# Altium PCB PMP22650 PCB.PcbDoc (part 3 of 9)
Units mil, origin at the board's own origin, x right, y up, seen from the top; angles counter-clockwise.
Board outline 11311 x 5233 mil, 8 copper layers (Layer 1, Layer 2, Layer 3, Layer 4, Layer 5, Layer 6, Layer 7, Layer 8), stack 88.6 mil thick; 633 components, 410 nets, 2503 pads, 1993 vias.
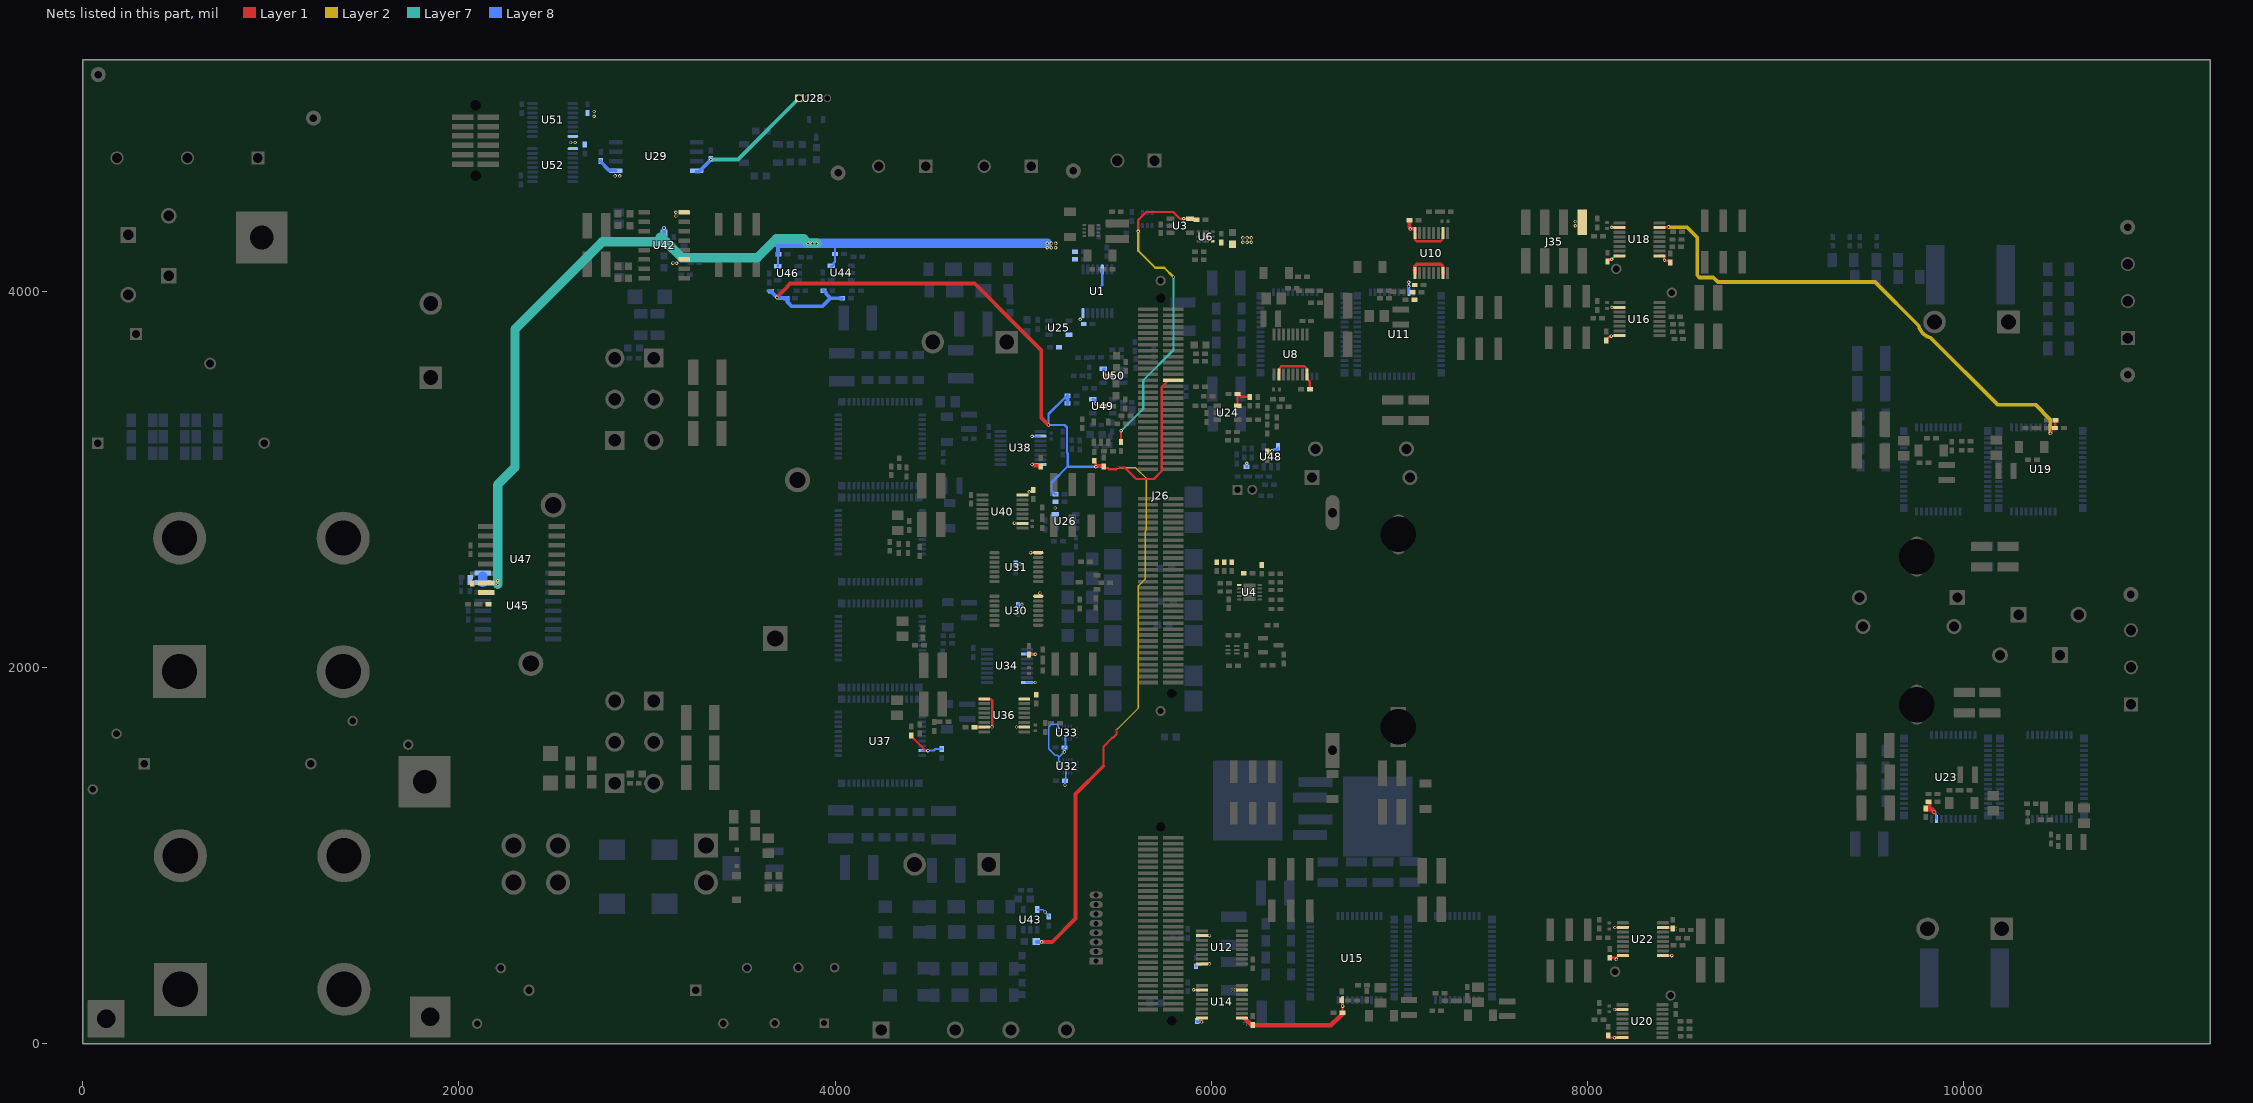
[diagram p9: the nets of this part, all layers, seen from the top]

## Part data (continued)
C44 C59 C66 C81 C88 C103 C110 C125 C152 C167 C174 C189: library part CMP-0750154-1, "CAP, CERM, 10 µF, 25 V,+/- 10%, X7R, AEC-Q200 Grade 1, 1206", Cap_Case=1206, Manufacturer="Taiyo Yuden", TempCo=X7R, Tolerance_%=10%, Value2=25V, ValueDisplayed=10µF
C45 C46 C49 C50 C67 C68 C71 C72 C89 C90 C93 C94 C111 C112 C115 C116 C153 C154 C157 C158 C175 C176 C179 C180 C256 C257: library part CMP-0084048-1, "CAP, CERM, 0.022 µF, 1000 V,+/- 10%, X7R, AEC-Q200 Grade 1, 1206", Cap_Case=1206, Manufacturer=Kemet, TempCo=X7R, Tolerance_%=10%, Value2=1000V, ValueDisplayed=0.022µF
C47 C48 C51 C52 C69 C70 C73 C74 C91 C92 C95 C96 C113 C114 C117 C118 C155 C156 C159 C160 C177 C178 C181 C182 C226 C227 C228 C229 C230 C231: library part CMP-0090548-1, "0.1µF ±10% 1000V (1kV) Ceramic Capacitor X7R 1812 (4532 Metric)", Digikey Part Number=399-16796-1-ND, Manufacturer=Kemet, Mouser Part Number=80-C1812X104KDRAUTO, Operating Temperature Range="-55°C to +125°C", TempCo=15%, Temperature Characteristic=X7R, Tolerance_%=10%, ValueDisplayed=0.1uF
C127 C130 C135 C237 C240: library part CMP-0064911-2, "CAP, CERM, 10 pF, 50 V,+/- 2.5%, C0G/NP0, AEC-Q200 Grade 1, 0402", Cap_Case=0402, Manufacturer=AVX, Supplier Part Number 1=478-5991-1-ND, TempCo=C0G/NP0, Tolerance_%=2.5%, Value1=Unknown, Value2=50V, ValueDisplayed=10pF
C128 C195 C238: library part CMP-0006317-2, "CAP, CERM, 2200 pF, 50 V, +/- 10%, X7R, AEC-Q200 Grade 1, 0402", Cap_Case=0402, Manufacturer=TDK, Supplier Part Number 1=445-5606-1-ND, TempCo=X7R, Tolerance_%=10%, Value1="1.07794 ohm", Value2=50V, ValueDisplayed=2200pF
C131: library part CMP-0006360-2, "CAP, CERM, 470 pF, 50 V, +/- 10%, X7R, AEC-Q200 Grade 1, 0402", Cap_Case=0402, Manufacturer=MuRata, Supplier Part Number 1=490-4913-1-ND, TempCo=X7R, Tolerance_%=10%, Value1=Unknown, Value2=50V, ValueDisplayed=470pF
C138: library part CMP-0007088-4, "CAP, CERM, 4700 pF, 100 V, +/- 10%, X7R, AEC-Q200 Grade 1, 0603", Cap_Case=0603, Manufacturer=TDK, Supplier Part Number 1=445-5810-1-ND, TempCo=X7R, Tolerance_%=10%, Value1="0.469862 ohm", Value2=100V, ValueDisplayed=4700pF
C141 C207 C210: library part CMP-0007127-4, "CAP, CERM, 470 pF, 50 V, +/- 5%, C0G/NP0, AEC-Q200 Grade 1, 0603", Cap_Case=0603, Manufacturer=MuRata, Supplier Part Number 1=490-4965-1-ND, TempCo=C0G/NP0, Tolerance_%=5%, Value1=Unknown, Value2=50V, ValueDisplayed=470pF
C190 C199: library part CMP-0076706-1, "CAP, CERM, 4.7 µF, 25 V,+/- 10%, X7R, AEC-Q200 Grade 1, 0805", Cap_Case=2x1.25x1.25mm, Manufacturer=TDK, Supplier Part Number 1=445-6967-1-ND, TempCo=X7R, Tolerance_%=10%, Value2=25V, ValueDisplayed=4.7µF
C191 C198 C200: library part CMP-0007077-5, "CAP, CERM, 0.1 uF, 25 V, +/- 10%, X7R, AEC-Q200 Grade 1, 0603", Cap_Case=0603, Manufacturer=TDK, Supplier Part Number 1=445-5667-1-ND, TempCo=X7R, Tolerance_%=10%, Value1=Unknown, Value2=25V, ValueDisplayed=0.1uF
C192 C201: library part CMP-0006849-4, "CAP, CERM, 0.01 uF, 25 V, +/- 5%, C0G/NP0, AEC-Q200 Grade 1, 0603", Cap_Case=0603, Manufacturer=Kemet, Supplier Part Number 1=399-14102-1-ND, TempCo=C0G/NP0, Tolerance_%=5%, Value1=Unknown, Value2=25V, ValueDisplayed=0.01uF
C193 C194: library part CMP-0007075-4, "CAP, CERM, 100 pF, 50 V, +/- 5%, C0G/NP0, AEC-Q200 Grade 0, 0603", Cap_Case=0603, Manufacturer=TDK, Supplier Part Number 1=445-12386-1-ND, TempCo=C0G/NP0, Tolerance_%=5%, Value1=Unknown, Value2=50V, ValueDisplayed=100pF
C196 C197: library part CMP-0006314-2, "CAP, CERM, 1000 pF, 50 V, +/- 10%, X7R, AEC-Q200 Grade 1, 0402", Cap_Case=0402, Manufacturer=TDK, Supplier Part Number 1=445-5605-1-ND, TempCo=X7R, Tolerance_%=10%, Value1="2.25564 ohm", Value2=50V, ValueDisplayed=1000pF
C204 C211: library part CMP-0006308-2, "CAP, CERM, 100 pF, 50 V, +/- 5%, C0G/NP0, AEC-Q200 Grade 1, 0402", Cap_Case=0402, Manufacturer=TDK, Supplier Part Number 1=445-5596-1-ND, TempCo=C0G/NP0, Tolerance_%=5%, Value1=Unknown, Value2=50V, ValueDisplayed=100pF
C208 C215: library part CMP-0006237-2, "CAP, CERM, 0.1 uF, 16 V, +/- 10%, X7R, AEC-Q200 Grade 1, 0402", Cap_Case=0402, Manufacturer=Kemet, Supplier Part Number 1=399-6828-1-ND, TempCo=X7R, Tolerance_%=10%, Value1=Unknown, Value2=16V, ValueDisplayed=0.1uF
C213: library part CMP-0006844-4, "CAP, CERM, 1000 pF, 50 V, +/- 5%, X7R, AEC-Q200 Grade 1, 0603", Cap_Case=0603, Manufacturer=Kemet, Supplier Part Number 1=399-12989-1-ND, TempCo=X7R, Tolerance_%=5%, Value1=Unknown, Value2=50V, ValueDisplayed=1000pF
C214: library part CMP-0007965-2, "CAP, CERM, 10 uF, 16 V, +/- 10%, X7S, AEC-Q200 Grade 1, 0805", Cap_Case=0805, Manufacturer=TDK, Supplier Part Number 1=445-16110-1-ND, TempCo=X7S, Tolerance_%=10%, Value1=Unknown, Value2=16V, ValueDisplayed=10uF
C216 C217 C221 C222 C235: library part CMP-0009589-2, "CAP, CERM, 4700 pF, 300 V, +/- 20%, Y5U, AEC-Q200 Grade 1, D13xT5mm", Cap_Case=13x5mm, Manufacturer=Vishay-Bccomponents, Supplier Part Number 1=BC2916-ND, TempCo=Y5U, Tolerance_%=20%, Value1=Unknown, Value2=300V, ValueDisplayed=4700pF
C218 C219 C220: library part CMP-0090606-1, "2.2µF Film Capacitor 305V 630V Polypropylene (PP), Metallized Radial", Digikey Part Number=495-7043-ND, Manufacturer=TDK, Operating Temperature Range="to +110°C", Tolerance_%=20%, ValueDisplayed=2.2uF, Voltage Ac Rating X=305V
C223 C224 C225: library part CMP-0090234-1, "470µF 500V Aluminum Electrolytic Capacitors Radial, Can - Snap-In 532.2mOhm @ 100Hz 15000 Hrs @ 85°C", Digikey Part Number=399-17944-ND, Leakage Current=6uA, Manufacturer=Kemet, Mouser Part Number=80-ALA7DA471DE500, Operating Temperature Range="-40°C to +85°C", Tolerance_%=20%, ValueDisplayed=470uF
C232: library part CMP-0006307-2, "CAP, CERM, 10 pF, 50 V, +/- 5%, C0G/NP0, AEC-Q200 Grade 1, 0402", Cap_Case=0402, Manufacturer=TDK, Supplier Part Number 1=445-5584-1-ND, TempCo=C0G/NP0, Tolerance_%=5%, Value1=Unknown, Value2=50V, ValueDisplayed=10pF
C233: library part CMP-0006310-2, "CAP, CERM, 150 pF, 50 V, +/- 5%, C0G/NP0, AEC-Q200 Grade 1, 0402", Cap_Case=0402, Manufacturer=TDK, Supplier Part Number 1=445-5598-1-ND, TempCo=C0G/NP0, Tolerance_%=5%, Value1=Unknown, Value2=50V, ValueDisplayed=150pF
C234: library part CMP-0090605-2, "100pF ±10% 440VAC Ceramic Capacitor Y5S Radial, Disc", Digikey Part Number=BC2908-ND, Manufacturer=Vishay, Mouser Part Number=72-AY2101K29Y5SS63L7, Operating Temperature Range="-55°C to +125°C", Temperature Characteristic=Y5S, Tolerance_%=10%, ValueDisplayed=100pF, Voltage Ac Rating X=X1, Voltage Ac Rating Y=Y2
C241 C246: library part CMP-0006328-2, "CAP, CERM, 0.022 uF, 50 V, +/- 10%, X7R, AEC-Q200 Grade 1, 0402", Cap_Case=0402, Manufacturer=TDK, Supplier Part Number 1=445-6895-1-ND, TempCo=X7R, Tolerance_%=10%, Value1="0.141987 ohm", Value2=50V, ValueDisplayed=0.022uF
C242 C243 C245 C247 C248 C250: library part CMP-0006324-2, "CAP, CERM, 0.01 uF, 50 V, +/- 10%, X7R, AEC-Q200 Grade 1, 0402", Cap_Case=0402, Manufacturer=TDK, Supplier Part Number 1=445-6893-1-ND, TempCo=X7R, Tolerance_%=10%, Value1="0.333065 ohm", Value2=50V, ValueDisplayed=0.01uF
D1: library part CMP-0005919-3, "Diode, TVS, Bi, 24 V, SOT-23", Manufacturer="ON Semiconductor", Value1=350W
D2 D3: library part CMP-0090591-1, "Diode Schottky 40V 3A Surface Mount SMA", Digikey Part Number=NRVBA340T3GOSCT-ND, Forward Current=3A, Manufacturer="ON Semiconductor", Max Surge Forward Current=100A, Mouser Part Number=863-NRVBA340T3G, Operating Temperature Range="-55°C to +150°C", Peak Reverse Current=0.3mA
D4 D5 D6 D7: library part CMP-0089095-1, "Diode Standard 1000V 1A Surface Mount D-Flat", Digikey Part Number=US1MDFQ-13DICT-ND, Forward Current=1A, Manufacturer=Diodes, Max Surge Forward Current=30A, Mouser Part Number=621-US1MDFQ-13, Operating Temperature Range="-55°C to +150°C", Peak Reverse Current=5uA, ValueDisplayed=10pF
D8: library part CMP-0028882-2, "Diode, Schottky, 40 V, 0.75 A, AEC-Q101, SOD-323", Manufacturer="Infineon Technologies", Value1=0.75A, Value2=0.74V
D9: library part CMP-0065110-3, "Diode, Zener, 5.1 V, 500 mW, AEC-Q101, SOD-123", Manufacturer=Vishay-Semiconductor, Power_W=500mW, Value1=0.5W
D10: library part CMP-0090610-1, "Bridge Rectifier Single Phase Standard 600V Through Hole TS-6P", Digikey Part Number=TS40P05GHD2G-ND, Forward Current=40A, Manufacturer="Taiwan Semiconductor", Max Surge Forward Current=400A, Mouser Part Number=821-TS40P05GHD2G, Operating Temperature Range="-55°C to +150°C", Peak Reverse Current=10uA
F1 F2 F3 F4: library part CMP-4956-0000-1, "25A AC 450V DC Fuse Cartridge, Ceramic Through Hole 3AB, 3AG, 1/4\" x 1-1/4\" (Axial)", Digikey Part Number=F10249-ND, Fuse Current=25A, Fuse Interrupt Dc Current=10000A, Manufacturer=Littelfuse, Mouser Part Number=576-0525025.MXEP, Operating Temperature Range="-55°C to +125°C"
J1: library part CMP-0090793-1, "Connector Header Through Hole 2 position 0.079\" (2.00mm)", Current_A=4A, Digikey Part Number=A98588-ND, Manufacturer="TE Connectivity", Mouser Part Number=571-2921612, Operating Temperature Range="-40°C to +221°C", Voltage_V=125V
J2 J3 J4 J5 J6 J8 J9 J11: library part CMP-0075177-1, "JUMPER TIN SMD, SMT", Current_A=10A, Manufacturer=Harwin, Supplier Part Number 1=952-1474-1-ND
J7 J10: library part CMP-0054983-1, "Receptacle, 3x1, 5mm, R/A, TH", Color=Green, Current_A=24A, Manufacturer="On Shore Technology Inc.", PartNumber=ED700/3, Voltage_V=300V
J12 J16 J18 J20 J22 J27 J29 J31 J36: library part CMP-0055666-1, "Receptacle, 2.54mm, 3x2, Tin, SMT", Color=Black, Current_A=5.7A, Manufacturer=Samtec, Supplier Part Number 1=82P2245
J13 J17 J19 J21 J23 J28 J30 J32: library part CMP-0090790-1, "4 Position Receptacle Connector  Surface Mount", Current_A=4.7A, Digikey Part Number=SSW-102-22-F-D-VS-ND, Manufacturer=Samtec, Mouser Part Number=200-SSW10222FDVS, Operating Temperature Range="-55°C to +125°C", Voltage_V=655V
J15: library part CMP-0054978-1, "Therminal Block, 5 mm, 2-pole, Tin, TH", Manufacturer="On Shore Technology Inc.", PartNumber=ED700/2
J24: library part CMP-0075601-2, "Header(Shrouded), 1.27mm, 6x2, Tin, SMT", Color=Black, Current_A=3.2A, Manufacturer=Samtec, Voltage_V=250V
J25: library part CMP-0003859-2, "C2000 controlCARD-180HSEC (60-pin addon) connector, SMT", Manufacturer=Samtec
J26: library part CMP-0003814-2, "C2000 controlCARD-120HSEC connector, SMT", Manufacturer=Samtec
J33: library part CMP-0055493-1, "Terminal Block, 3x1, 9.52MM, TH", Manufacturer="Phoenix Contact", Supplier Part Number 1=277-1272-ND
J34: library part CMP-0055072-1, "Female Connector, 8x1, 1.27 mm, Black, Tin, TH", Manufacturer=Mill-Max, Supplier Part Number 1=ED90570-ND
J35: library part CMP-0090885-1, "8 Position Receptacle Connector  Surface Mount", Current_A=4.7A, Digikey Part Number=SSW-104-22-F-D-VS-K-ND, Manufacturer=Samtec, Mouser Part Number=200-SSW10422FDVSK, Operating Temperature Range="-55°C to +125°C", Voltage_V=655V
J37 J38: library part CMP-0055505-1, "Terminal Block, 2x1, 6.35mm, Green, TH", Color=Green, Manufacturer="Phoenix Contact", Supplier Part Number 1=277-1269-ND
K1: library part CMP-0090589-1, "Relay Automotive SPST-NO 32A 12VDC 160 Ohm Through Hole", Coil Power_W=440mW, Coil Resistance=160Ω, Coil Voltage_VDC=12V, Contact Rating_A=32A, Manufacturer=Fujitsu, Max Power Dissipation=900mW, Operating Temperature Range="-40°C to +105°C", Switching Current=40A
L2: library part CMP-0056750-1, "Inductor, Shielded, Ferrite, 2.2 uH, 1.7 A, 0.072 ohm, AEC-Q200 Grade 1, SMD", Manufacturer=Bourns, Supplier Part Number 1=SRN3015TA-2R2MCT-ND, Value1="0.072 ohm", Value2=1.7A, ValueDisplayed=2.2uH
L3 L4 L5 L6 L7 L8 L9 L10 L12 L13 L14 L15: library part CMP-0090507-1, "4.7µH Shielded Molded Inductor 1.22A 262mOhm Max 1008 (2520 Metric)", Digikey Part Number=283-4799-1-ND, Manufacturer=Eaton, Mouser Part Number=704-MPIA2510V2-4R7-R, Operating Temperature Range="-40°C to +125°C", Self Resonant Frequency=25MHz, Test Frequency=1MHz, Tolerance_%=20%
L11: library part CMP-0062430-2, "Inductor, Ferrite, 100 uH, 0.15 A, 2 ohm, SMD", Manufacturer=TDK, Supplier Part Number 1=445-3959-1-ND, Value1="2 ohm", Value2=0.15A, ValueDisplayed=100uH
L16 L17: library part CMP-0090759-1, "Common Mode Choke", Manufacturer="Renco Electronics", Operating Temperature Range=to, Test Frequency=10kHz
L18: library part CMP-0091444-1, "Coupled PFC", Manufacturer=Cyntec, Operating Temperature Range=to, Test Frequency=100kHz
L19: library part CMP-0090978-1, "OBC Resonant Inductor", Manufacturer=Cyntec, Operating Temperature Range=to, Test Frequency=500kHz
LBL1: library part CMP-0003625-1, "Thermal Transfer Printable Labels, 0.650\" W x 0.200\" H - 10,000 per roll", Manufacturer=Brady, Supplier Part Number 1=97C5133
Logo1: library part CMP-0074838-1, "Texas Instrument Corporate Signature"
Logo2: library part CMP-0074847-1, "FCC_disclaimer"
Logo3: library part CMP-0074769-1
Logo4: library part CMP-0074844-1
LOGO5 LOGO9: library part CMP-0074835-1, "IEC 61010-1 High Voltage Warning"
LOGO6 LOGO8: library part CMP-0074837-1, "IEC 61010-1 Hot Surface Warning"
MP1: library part CMP-0090997-2, "Shield", Manufacturer="Texas Instruments", Operating Temperature Range=to
Q1 Q2: library part CMP-0090447-1, "N-Channel 800V 17A (Tc) 227W (Tc) Surface Mount PG-TO263-3-2", Digikey Part Number=IPB80R290C3AATMA2-ND, Drain To Source Breakdown Voltage=800V, Input Capacitace At Vds="2300pF @ 100V", Manufacturer="Infineon Technologies", Mouser Part Number=726-IPB80R290C3AATMA, Operating Temperature Range="-40°C to +150°C", Power_W=227W, Pulse Drain Current=51A, Typ Forward Diode Voltage=1V
Q3: library part CMP-0077248-1, "MOSFET, N-CH, 20 V, 2.3 A, AEC-Q101, SOT-23", Alternate Manufacturer=None, Manufacturer="Infineon Technologies", Supplier Part Number 1=BSS806NEH6327XTSA1CT-ND, Value1="? ohm", Value2="1.7 nC"
Q4: library part CMP-0090551-1, "P-Channel 30V 3A (Tc) 3W (Tc) Surface Mount SC-70-6 (SOT-363)", Digikey Part Number=SQ1431EH-T1_GE3CT-ND, Drain To Source Breakdown Voltage=-30V, Input Capacitace At Vds="164pF @ -25V", Manufacturer=Vishay, Mouser Part Number=78-SQ1431EH-T1_GE3, Operating Temperature Range="-55°C to +175°C", Power_W=3W, Pulse Drain Current=-12A, Typ Forward Diode Voltage=-0.85V
Q5: library part CMP-0000888-1, "MOSFET, N-CH, 70 V, 3.8 A, AEC-Q101, SOT-223", Alternate Manufacturer=None, Manufacturer="Diodes Inc.", Supplier Part Number 1=ZXMN7A11GCT-ND, Value1=0.1, Value2="7.4 nC"
Q6 Q7 Q8 Q9: library part CMP-0090619-2, "N-Channel 650V 75A (Tc) 595W (Tc) Through Hole TO-247-3", Digikey Part Number=NVHL025N65S3-ND, Drain To Source Breakdown Voltage=713V, Input Capacitace At Vds="7330pF @ 400V", Manufacturer="ON Semiconductor", Mouser Part Number=863-NVHL025N65S3, Operating Temperature Range="-55°C to +150°C", Power_W=595W, Pulse Drain Current=187.5A, Typ Forward Diode Voltage=0.88V
Q10: library part CMP-0000777-1, "MOSFET, N-CH, 60 V, 0.32 A, AEC-Q101, SOT-23", Alternate Manufacturer=None, Manufacturer="ON Semiconductor", Supplier Part Number 1=2V7002KT1GOSCT-ND, Value1=2, Value2="0.7 nC"
R1 R2 R3 R4 R5: library part CMP-0018567-2, "RES, 0.006, 1%, 0.5 W, 1206", Manufacturer=Vishay-Dale, Power_W=500mW, Supplier Part Number 1=WSLD-.006CT-ND, TempCo="110 ppm/C", Tolerance_%=1%, Value2=0.5W, Value_Code=6L000, ValueDisplayed=0.006
R6 R8: library part CMP-0026463-2, "RES, 5.11 k, 1%, 0.063 W, AEC-Q200 Grade 0, 0402", Manufacturer=Vishay-Dale, Power_W=63mW, Supplier Part Number 1=541-5.11KLCT-ND, TempCo="100 ppm/C", Tolerance_%=1%, Value2=0.063W, Value_Code=5k11, ValueDisplayed=5.11k
R7: library part CMP-0026764-1, "RES, 10.0, 1%, 0.063 W, AEC-Q200 Grade 0, 0402", Manufacturer="Stackpole Electronics Inc", Power_W=63mW, Supplier Part Number 1=RMCF0402JT10R0CT-ND, TempCo="100 ppm/C", Tolerance_%=1%, Value2=0.063W, Value_Code=10R0, ValueDisplayed=10.0
R9 R19 R24 R27 R32 R37 R42 R47 R52 R57 R62 R98 R103 R108 R113 R204: library part CMP-0026992-3, "RES, 0, 5%, 0.1 W, AEC-Q200 Grade 0, 0402", Manufacturer=Panasonic, Power_W=100mW, Supplier Part Number 1=P0.0JCT-ND, TempCo="600 ppm/C", Tolerance_%=5%, Value2=0.1W, Value_Code=0000, ValueDisplayed=0
R10 R11 R12 R13 R14 R15 R17 R18 R20 R22 R66 R71 R78 R82 R178 R183 R203: library part CMP-0078779-1, "RES, 10.0 k, 1%, 0.2 W, AEC-Q200 Grade 0, 0402", Manufacturer=Panasonic, Power_W=200mW, Supplier Part Number 1=P17230CT-ND, TempCo="100 ppm/C", Tolerance_%=1%, Value2=0.2W, Value_Code=10k0, ValueDisplayed=10.0k
R16 R69 R70: library part CMP-0026071-3, "RES, 1.00 k, 1%, 0.063 W, AEC-Q200 Grade 0, 0402", Manufacturer=Vishay-Dale, Power_W=63mW, Supplier Part Number 1=541-1.00KLCT-ND, TempCo="100 ppm/C", Tolerance_%=1%, Value2=0.063W, Value_Code=1k00, ValueDisplayed=1.00k
R21: library part CMP-0026048-3, "RES, 178 k, 1%, 0.063 W, AEC-Q200 Grade 0, 0402", Manufacturer=Vishay-Dale, Power_W=63mW, Supplier Part Number 1=541-178KLCT-ND, TempCo="100 ppm/C", Tolerance_%=1%, Value2=0.063W, Value_Code=178k
R23: library part CMP-0026768-2, "RES, 100 k, 0.5%, 0.063 W, AEC-Q200 Grade 0, 0402", Manufacturer=Vishay-Dale, Power_W=63mW, Supplier Part Number 1=541-100KAVCT-ND, TempCo="50 ppm/C", Tolerance_%=0.5%, Value2=0.063W, Value_Code=100k
R25: library part CMP-0026611-3, "RES, 953 k, 1%, 0.063 W, AEC-Q200 Grade 0, 0402", Manufacturer=Vishay-Dale, Power_W=63mW, Supplier Part Number 1=541-953KLCT-ND, TempCo="100 ppm/C", Tolerance_%=1%, Value2=0.063W, Value_Code=953k
R26 R31 R36 R41 R46 R51 R56 R61 R97 R102 R107 R112: library part CMP-0026510-2, "RES, 69.8 k, 1%, 0.063 W, AEC-Q200 Grade 0, 0402", Manufacturer=Vishay-Dale, Power_W=63mW, Supplier Part Number 1=541-69.8KLCT-ND, TempCo="100 ppm/C", Tolerance_%=1%, Value2=0.063W, Value_Code=69k8, ValueDisplayed=69.8k
R28 R33 R38 R43 R48 R53 R58 R63 R99 R104 R109 R114 R131 R137 R138 R146 R153 R155: library part CMP-0025958-3, "RES, 10.0 k, 1%, 0.063 W, AEC-Q200 Grade 0, 0402", Manufacturer=Vishay-Dale, Power_W=63mW, Supplier Part Number 1=541-10.0KLCT-ND, TempCo="100 ppm/C", Tolerance_%=1%, Value2=0.063W, Value_Code=10k0, ValueDisplayed=10.0k
R29 R34 R39 R44 R49 R54 R59 R64 R100 R105 R110 R115: library part CMP-0026902-3, "RES, 300, 5%, 0.063 W, AEC-Q200 Grade 0, 0402", Manufacturer=Vishay-Dale, Power_W=63mW, Supplier Part Number 1=541-300JCT-ND, TempCo="200 ppm/C", Tolerance_%=5%, Value2=0.063W, Value_Code=300R, ValueDisplayed=300
R30 R35 R40 R45 R50 R55 R60 R65 R101 R106 R111 R116: library part CMP-0026404-2, "RES, 49.9, 1%, 0.063 W, AEC-Q200 Grade 0, 0402", Manufacturer=Vishay-Dale, Power_W=63mW, Supplier Part Number 1=541-49.9LCT-ND, TempCo="100 ppm/C", Tolerance_%=1%, Value2=0.063W, Value_Code=49R9, ValueDisplayed=49.9
R67 R176 R179 R205 R206 R207 R208: library part CMP-0026822-3, "RES, 0, 5%, 0.063 W, AEC-Q200 Grade 0, 0402", Manufacturer=Vishay-Dale, Power_W=63mW, Supplier Part Number 1=541-0.0JCT-ND, TempCo="200 ppm/C", Tolerance_%=5%, Value2=0.063W, Value_Code=0000, ValueDisplayed=0
R68 R81 R180: library part CMP-0026454-2, "RES, 56.2, 1%, 0.063 W, AEC-Q200 Grade 0, 0402", Manufacturer=Vishay-Dale, Power_W=63mW, Supplier Part Number 1=541-56.2LCT-ND, TempCo="100 ppm/C", Tolerance_%=1%, Value2=0.063W, Value_Code=56R2, ValueDisplayed=56.2
R72: library part CMP-0026337-2, "RES, 3.65 k, 1%, 0.063 W, AEC-Q200 Grade 0, 0402", Manufacturer=Vishay-Dale, Power_W=63mW, Supplier Part Number 1=541-3.65KLCT-ND, TempCo="100 ppm/C", Tolerance_%=1%, Value2=0.063W, Value_Code=3k65, ValueDisplayed=3.65k
R73 R91 R141 R147: library part CMP-0022599-4, "RES, 7.15 k, 1%, 0.1 W, AEC-Q200 Grade 0, 0603", Manufacturer=Vishay-Dale, Power_W=100mW, Supplier Part Number 1=541-7.15KHCT-ND, TempCo="100 ppm/C", Tolerance_%=1%, Value2=0.1W, Value_Code=7k15, ValueDisplayed=7.15k
R74 R80 R130 R133 R148: library part CMP-0026070-3, "RES, 19.6, 1%, 0.063 W, AEC-Q200 Grade 0, 0402", Manufacturer=Vishay-Dale, Power_W=63mW, Supplier Part Number 1=541-19.6LCT-ND, TempCo="100 ppm/C", Tolerance_%=1%, Value2=0.063W, Value_Code=19R6, ValueDisplayed=19.6
R75 R76 R77 R94 R95 R96 R127 R128 R129 R134 R135 R136 R142 R143 R144 R150 R151 R152: library part CMP-0016927-3, "RES, 365 k, 1%, 0.25 W, AEC-Q200 Grade 0, 1206", Manufacturer=Vishay-Dale, Power_W=250mW, Supplier Part Number 1=541-365KFCT-ND, TempCo="100 ppm/C", Tolerance_%=1%, Value2=0.25W, Value_Code=365k
R79 R83: library part CMP-0026021-3, "RES, 150 k, 1%, 0.063 W, AEC-Q200 Grade 0, 0402", Manufacturer=Vishay-Dale, Power_W=63mW, Supplier Part Number 1=541-150KLCT-ND, TempCo="100 ppm/C", Tolerance_%=1%, Value2=0.063W, Value_Code=150k
R84 R89 R90 R92 R93: library part CMP-0025874-4, "RES, 0, 5%, 0.1 W, AEC-Q200 Grade 0, 0603", Manufacturer=Panasonic, Power_W=100mW, Supplier Part Number 1=P0.0GCT-ND, TempCo="600 ppm/C", Tolerance_%=5%, Value2=0.1W, Value_Code=0000, ValueDisplayed=0
R85 R88: library part CMP-0023343-3, "RES, 0, 1%, 0.1 W, AEC-Q200 Grade 0, 0603", Manufacturer="Stackpole Electronics Inc", Power_W=100mW, Supplier Part Number 1=RMCF0603ZT0R00CT-ND, TempCo=ppm/C, Tolerance_%=1%, Value2=0.1W, Value_Code=0
R86 R87: library part CMP-0022532-4, "RES, 60.4 k, 1%, 0.1 W, AEC-Q200 Grade 0, 0603", Manufacturer=Vishay-Dale, Power_W=100mW, Supplier Part Number 1=541-60.4KHCT-ND, TempCo="100 ppm/C", Tolerance_%=1%, Value2=0.1W, Value_Code=60k4, ValueDisplayed=60.4k
R117 R121: library part CMP-0016745-3, "RES, 1.00, 1%, 0.25 W, AEC-Q200 Grade 0, 1206", Manufacturer=Vishay-Dale, Power_W=250mW, Supplier Part Number 1=53K1855, TempCo="100 ppm/C", Tolerance_%=1%, Value2=0.25W, Value_Code=1R00, ValueDisplayed=1.00
R118 R122: library part CMP-0025701-4, "RES, 10 k, 5%, 0.1 W, AEC-Q200 Grade 0, 0603", Manufacturer=Vishay-Dale, Power_W=100mW, Supplier Part Number 1=541-10KGCT-ND, TempCo="200 ppm/C", Tolerance_%=5%, Value2=0.1W, Value_Code=10k0, ValueDisplayed=10k
R119 R124: library part CMP-0017092-3, "RES, 5.11, 1%, 0.25 W, AEC-Q200 Grade 0, 1206", Manufacturer=Vishay-Dale, Power_W=250mW, Supplier Part Number 1=541-5.11FFCT-ND, TempCo="100 ppm/C", Tolerance_%=1%, Value2=0.25W, Value_Code=5R11, ValueDisplayed=5.11
R120 R123: library part CMP-0027007-2, "RES, 0, 5%, 0.063 W, AEC-Q200 Grade 0, 0402", Manufacturer="KOA Speer", Power_W=63mW, Supplier Part Number 1=660-RK73Z1ETTP, TempCo=ppm/C, Tolerance_%=5%, Value2=0.063W, Value_Code=0000, ValueDisplayed=0
R125 R139: library part CMP-0022377-4, "RES, 3.48 k, 1%, 0.1 W, AEC-Q200 Grade 0, 0603", Manufacturer=Vishay-Dale, Power_W=100mW, Supplier Part Number 1=541-3.48KHCT-ND, TempCo="100 ppm/C", Tolerance_%=1%, Value2=0.1W, Value_Code=3k48, ValueDisplayed=3.48k
R126 R140 R145 R154: library part CMP-0026041-3, "RES, 16.5 k, 1%, 0.063 W, AEC-Q200 Grade 0, 0402", Manufacturer=Vishay-Dale, Power_W=63mW, Supplier Part Number 1=541-16.5KLCT-ND, TempCo="100 ppm/C", Tolerance_%=1%, Value2=0.063W, Value_Code=16k5, ValueDisplayed=16.5k
R132 R149: library part CMP-0026335-2, "RES, 3.48 k, 1%, 0.063 W, AEC-Q200 Grade 0, 0402", Manufacturer=Vishay-Dale, Power_W=63mW, Supplier Part Number 1=541-3.48KLCT-ND, TempCo="100 ppm/C", Tolerance_%=1%, Value2=0.063W, Value_Code=3k48, ValueDisplayed=3.48k
R156: library part CMP-0021998-4, "RES, 10.0 k, 1%, 0.1 W, AEC-Q200 Grade 0, 0603", Manufacturer=Vishay-Dale, Power_W=100mW, Supplier Part Number 1=541-10.0KHCT-ND, TempCo="100 ppm/C", Tolerance_%=1%, Value2=0.1W, Value_Code=10k0, ValueDisplayed=10.0k
R157 R158: library part CMP-0018707-3, "RES, 5.1, 5%, 0.25 W, AEC-Q200 Grade 0, 1206", Manufacturer=Vishay-Dale, Power_W=250mW, Supplier Part Number 1=541-5.1ECT-ND, TempCo="200 ppm/C", Tolerance_%=5%, Value2=0.25W, Value_Code=5R10, ValueDisplayed=5.1
R159 R164 R166 R171 R172: library part CMP-0086941-2, "10 mOhms ±1% 1W Chip Resistor 1206 (3216 Metric) Automotive AEC-Q200, Current Sense, Moisture Resistant Metal Element", Manufacturer=Bourns, Power_W=1W, TempCo=50ppm/°C, Tolerance_%=1%, ValueDisplayed=10m
R160 R165: library part CMP-0090612-1, "PTC Thermistors 30Vdc 185mA 13ohms PTC Overcurrent", Digikey Part Number=495-76340-1-ND, Manufacturer=TDK, Max Current=90mA, Mouser Part Number=871-B59101P1080A062, Operating Temperature Range="-40°C to +125°C", Tolerance_%=25%
R161 R162 R163 R167 R168 R169 R173 R174 R175: library part CMP-0018656-3, "RES, 330 k, 5%, 0.25 W, AEC-Q200 Grade 0, 1206", Manufacturer=Vishay-Dale, Power_W=250mW, Supplier Part Number 1=541-330KECT-ND, TempCo="200 ppm/C", Tolerance_%=5%, Value2=0.25W, Value_Code=330k
R170: library part CMP-0090617-1, "820V 10kA Varistor 1 Circuit Through Hole Disc 20mm", Clamping Voltage=1355V, Digikey Part Number=F10974-ND, Manufacturer=Littelfuse, Mouser Part Number=576-V20H510AUTO, Operating Temperature Range="-40°C to +125°C", ValueDisplayed=350pF, Varistor Voltage=738V
R177: library part CMP-0026088-3, "RES, 1.50 k, 1%, 0.063 W, AEC-Q200 Grade 0, 0402", Manufacturer=Vishay-Dale, Power_W=63mW, Supplier Part Number 1=541-1.50KLCT-ND, TempCo="100 ppm/C", Tolerance_%=1%, Value2=0.063W, Value_Code=1k50, ValueDisplayed=1.50k
R181 R182: library part CMP-0026448-2, "RES, 549, 1%, 0.063 W, AEC-Q200 Grade 0, 0402", Manufacturer=Vishay-Dale, Power_W=63mW, Supplier Part Number 1=541-549LCT-ND, TempCo="100 ppm/C", Tolerance_%=1%, Value2=0.063W, Value_Code=549R, ValueDisplayed=549
R184: library part CMP-0026084-3, "RES, 1.37 k, 1%, 0.063 W, AEC-Q200 Grade 0, 0402", Manufacturer=Vishay-Dale, Power_W=63mW, Supplier Part Number 1=541-1.37KLCT-ND, TempCo="100 ppm/C", Tolerance_%=1%, Value2=0.063W, Value_Code=1k37, ValueDisplayed=1.37k
R185 R191: library part CMP-0022636-4, "RES, 8.45 k, 1%, 0.1 W, AEC-Q200 Grade 0, 0603", Manufacturer=Vishay-Dale, Power_W=100mW, Supplier Part Number 1=541-8.45KHCT-ND, TempCo="100 ppm/C", Tolerance_%=1%, Value2=0.1W, Value_Code=8k45, ValueDisplayed=8.45k
R186 R187 R189 R190: library part CMP-0026238-2, "RES, 2.55 k, 1%, 0.063 W, AEC-Q200 Grade 0, 0402", Manufacturer=Vishay-Dale, Power_W=63mW, Supplier Part Number 1=541-2.55KLCT-ND, TempCo="100 ppm/C", Tolerance_%=1%, Value2=0.063W, Value_Code=2k55, ValueDisplayed=2.55k
R188 R198: library part CMP-0025979-3, "RES, 11.0, 1%, 0.063 W, AEC-Q200 Grade 0, 0402", Manufacturer=Vishay-Dale, Power_W=63mW, Supplier Part Number 1=541-11.0LCT-ND, TempCo="100 ppm/C", Tolerance_%=1%, Value2=0.063W, Value_Code=11R0, ValueDisplayed=11.0
R192: library part CMP-0017331-3, "RES, 12.4 k, 1%, 0.25 W, AEC-Q200 Grade 0, 1206", Manufacturer=Panasonic, Power_W=250mW, Supplier Part Number 1=P12.4KFCT-ND, TempCo="100 ppm/C", Tolerance_%=1%, Value2=0.25W, Value_Code=12k4, ValueDisplayed=12.4k
R193 R197 R201: library part CMP-0016861-3, "RES, 2.00 M, 1%, 0.25 W, AEC-Q200 Grade 0, 1206", Manufacturer=Vishay-Dale, Power_W=250mW, Supplier Part Number 1=541-2.00MFCT-ND, TempCo="100 ppm/C", Tolerance_%=1%, Value2=0.25W, Value_Code=2M00, ValueDisplayed=2.00M
R194 R202: library part CMP-0026553-2, "RES, 7.15 k, 1%, 0.063 W, AEC-Q200 Grade 0, 0402", Manufacturer=Vishay-Dale, Power_W=63mW, Supplier Part Number 1=541-7.15KLCT-ND, TempCo="100 ppm/C", Tolerance_%=1%, Value2=0.063W, Value_Code=7k15, ValueDisplayed=7.15k
R195 R196 R199 R200: library part CMP-0026938-5, "RES, 4.7 k, 5%, 0.063 W, AEC-Q200 Grade 0, 0402", Manufacturer=Vishay-Dale, Power_W=63mW, Supplier Part Number 1=541-4.7KJCT-ND, TempCo="200 ppm/C", Tolerance_%=5%, Value2=0.063W, Value_Code=4k70, ValueDisplayed=4.7k
R209 R210 R211 R212 R213 R214 R215 R216 R217 R218 R219 R220: library part CMP-0026827-3, "RES, 10, 5%, 0.063 W, AEC-Q200 Grade 0, 0402", Manufacturer=Vishay-Dale, Power_W=63mW, Supplier Part Number 1=541-10JCT-ND, TempCo="200 ppm/C", Tolerance_%=5%, Value2=0.063W, Value_Code=10R0, ValueDisplayed=10
T1: library part CMP-0090781-3, "TRANSFORMER", Manufacturer=Cyntec, Operating Temperature Range=to, Voltage_Isolation_Vrms=2000VDC
T2: library part CMP-0090959-1, "PRIMARY SIDE ROGOWSKI (PMP22495)", Manufacturer="Renco Electronics", Operating Temperature Range=to
T3: library part CMP-0090960-2, "Secondary Side Rogowski (PMP22495)", Manufacturer="Renco Electronics", Operating Temperature Range=to
TP1 TP2 TP5 TP6: library part CMP-0055138-1, "Test Point, Miniature, Black, TH", Color=Black, Manufacturer=Keystone, Supplier Part Number 1=36-5001-ND
TP3 TP7 TP8: library part CMP-0055137-1, "Test Point, Miniature, Red, TH", Color=Red, Manufacturer=Keystone, Supplier Part Number 1=36-5000-ND
U1 U30: library part CMP-0054468-2, "Automotive Catalog Dual 4-Input Positive-AND Gates, PW0014A, LARGE T&R", F @ Nom Voltage(Max)(Mhz)=70, Generic Part Number=SN74HC21-Q1, ICC @ Nom Voltage(Max)(mA)=0.02, Manufacturer="Texas Instruments", Operating Temperature Range(C)="-40 to 125", Rating=Automotive, tpd @ Nom Voltage(Max)(ns)=140, Voltage(Nom)(V)=5
U2: library part CMP-0073534-1, "3-MHz, Low-Power, Internal EMI Filter, RRIO, Operational Amplifier, DBV0005A (SOT-23-5)", Alternate Manufacturer="Texas Instruments", Alternate PartNumber=TLV314QDBVTQ1
U3: library part CMP-0090523-1, "Voltage References Automotive 12-ppm/ C low-noise low-power precision voltage reference", Manufacturer="Texas Instruments", Max Supply Voltage=5.5V, Min Supply Voltage=2.8V, Mouser Part Number=595-REF4132B33DBVRQ1, Nominal Supply Current=80uA, Operating Temperature Range="-40°C to +125°C", Output Voltage=3.3V
U4: library part CMP-0081428-2, "Automotive Precision Voltage Supervisor With Programmable Window Watchdog Timer, DRC0010R (VSON-10)", Alternate Manufacturer="Texas Instruments", Operating Temperature Range="-40 to 125 C", Rating=Automotive
U5: library part CMP-0750051-1, "Overvoltage and Undervoltage Reset IC With Time Delay and Manual Reset, DSE0006A (WSON-6)", Alternate Manufacturer="Texas Instruments"
U6: library part CMP-0090683-1, "Linear Voltage Regulator IC  1 Output  500mA 6-WSON (2x2)", Digikey Part Number=296-TPS74533PQWDRVRQ1CT-ND, Dropout Voltage=95mV, Manufacturer="Texas Instruments", Max Supply Voltage=6V, Min Supply Voltage=4.15V, Mouser Part Number=595-PS74533PQWDRVRQ1, Nominal Supply Current=25uA, Operating Temperature Range="-40°C to +125°C", Output Voltage=3.3V
U7: library part CMP-0067104-2, "3-17V 0.5A Automotive Step-Down Converter in 2x2 QFN package, DSG0008A (WSON-8)", Alternate Manufacturer="Texas Instruments", Alternate PartNumber=TPS62170QDSGTQ1
U8 U10 U12 U14 U16 U18 U20 U22 U34 U36 U38 U40: library part CMP-0090469-1, Digikey Part Number=296-51207-1-ND, Manufacturer="Texas Instruments", Max Supply Voltage=5.5V, Min Supply Voltage=2.25V, Mouser Part Number=595-ISO7741FQDBQRQ1, Nominal Supply Current=1.5-18mA, Operating Temperature Range="-40°C to +125°C"
U9 U11 U13 U15 U17 U19 U21 U23 U35 U37 U39 U41: library part CMP-0089968-2, "650-V 30-mΩ GaN FET with Integrated Driver and Protection", Manufacturer="Texas Instruments", Max Supply Voltage=18V, Min Supply Voltage=7.5V, Nominal Supply Current=540uA, Operating Temperature Range="-40°C to +125°C", Output Voltage=520V
U24 U48: library part CMP-0041005-2, "Automotive Catalog, 50 MHz, Low-Noise, Single-Supply Rail-to-Rail Operational Amplifier, 2.2 to 5.5 V, -40 to 125 degC, 5-pin SOT23 (DBV5), Green (RoHS & no Sb/Br)", Manufacturer="Texas Instruments", Total Supply Voltage(Max)(+5V is 5, +/-5V is 10)=5.5, Total Supply Voltage(Min)(+5V is 5, +/-5V is 10)=2.2
U25 U43 U44 U46 U49 U50: library part CMP-0077859-1, "Automotive Qualified Precision, Zero-Crossover, 20MHz, 0.9pA Ib, RRIO, CMOS Operational Amplifier, DBV0005A (SOT-23-5)", Alternate Manufacturer="Texas Instruments", Alternate PartNumber=OPA320AQDBVTQ1
U26: library part CMP-0068826-2, "17 MHz, Low Noise, CMOS Input, 1.8V Operational Amplifiers, DBV0005A (SOT-23-5)", Manufacturer="Texas Instruments", Operating Temperature Range="-40 to 125 C", Rating=Automotive
U27: library part CMP-0090472-1, "Temperature Sensor Analog, Local -40°C ~ 150°C 10mV/°C SOT-23-3", Digikey Part Number=296-TMP235AEDBZTQ1CT-ND, Manufacturer="Texas Instruments", Max Supply Voltage=5.5V, Min Supply Voltage=2.3V, Mouser Part Number=595-TMP235AEDBZTQ1, Operating Supply Current=9uA, Operating Temperature Range="-40°C to +150°C", Output Voltage=500mV
U28: library part CMP-0054569-1, "Header, 50mil, 4x1, Gold, TH", Manufacturer="Sullins Connector Solutions", Supplier Part Number 1=S9014E-04-ND
U29: library part CMP-0090614-1, "Isolated CAN Transceiver with 70V Bus Fault Protection and Flexible Data Rate 8-Pin SOIC T/R", Digikey Part Number=296-ISO1042BQDWVRQ1CT-ND, Manufacturer="Texas Instruments", Max Supply Voltage=5.5V, Min Supply Voltage=1.71V, Mouser Part Number=595-ISO1042BQDWVRQ1, Nominal Supply Current=1.2-43mA, Operating Temperature Range="-40°C to +125°C"
U31: library part CMP-0054514-2, "Automotive Catalog Quadruple 2-Input Positive-AND Gates, PW0014A, LARGE T&R", F @ Nom Voltage(Max)(Mhz)=70, Generic Part Number=SN74AHCT08Q-Q1, ICC @ Nom Voltage(Max)(mA)=0.02, Manufacturer="Texas Instruments", Operating Temperature Range(C)="-40 to 125", Rating=Automotive, tpd @ Nom Voltage(Max)(ns)=9, Voltage(Nom)(V)=5
U32 U33: library part CMP-0090592-1, "Automotive, 5-V bidirectional 8:1 multiplexer with 1.8-V logic", Manufacturer="Texas Instruments", Max Supply Voltage=5.5V, Min Supply Voltage=1.08V, Mouser Part Number=595-TMUX1208QRSVRQ1, Nominal Supply Current=0.02uA, On State Resistance=5Ω, Operating Temperature Range="-40°C to +125°C"
U42: library part CMP-0090594-2, "Half-Bridge Gate Driver IC CMOS/TTL 16-SOIC", Digikey Part Number=296-UCC21222QDRQ1CT-ND, Manufacturer="Texas Instruments", Max Power Dissipation=1825mW, Max Supply Voltage=5.5V, Min Supply Voltage=3V, Mouser Part Number=595-UCC21222QDRQ1, Nominal Supply Current=1-2.5mA, Operating Temperature Range="-40°C to +125°C", Output Voltage=9.2-18V
U45 U47: library part CMP-0090912-1, "Current Sensor 40A 1 Channel Hall Effect, Differential Bidirectional 16-SOIC (0.295\", 7.50mm Width)", Coil Resistance=1mΩ, Current Sensitivity=33mV/A, Digikey Part Number=620-1988-1-ND, Manufacturer="Allegro Microsystems", Max Sensing Current=40A, Max Supply Voltage=3.46V, Min Supply Voltage=3.14V, Operating Supply Current=20mA, Operating Temperature Range="to +165°C"
U51: library part CMP-0078425-1, "High Speed, Robust EMC, Reinforced Six-Channel Digital Isolator, DBQ0016A (SSOP-16)", Alternate Manufacturer="Texas Instruments", Alternate PartNumber=ISO7761DBQ
U52: library part CMP-0013038-3, "High Speed, Robust EMC Reinforced Triple-Channel Digital Isolator, DBQ0016A (SSOP-16)", Alternate Manufacturer="Texas Instruments", Alternate PartNumber=ISO7730DBQ
ZZ1: library part CMP-0077238-1
ZZ2: library part CMP-0077237-1
ZZ3: library part CMP-0077236-1
ZZ4: library part CMP-0003616-3

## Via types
v1: diameter 18, hole 10, Layer 1 to Layer 8, 1759 vias
v2: diameter 8, hole 4, Layer 1 to Layer 2, 160 vias
v3: diameter 18, hole 10, Layer 1 to Layer 8, tented both sides, 34 vias
v4: diameter 8, hole 4, Layer 7 to Layer 8, 28 vias
v5: diameter 19.68, hole 7.87, Layer 1 to Layer 8, 8 vias
v6: diameter 118.11, hole 86.61, Layer 1 to Layer 8, 4 vias

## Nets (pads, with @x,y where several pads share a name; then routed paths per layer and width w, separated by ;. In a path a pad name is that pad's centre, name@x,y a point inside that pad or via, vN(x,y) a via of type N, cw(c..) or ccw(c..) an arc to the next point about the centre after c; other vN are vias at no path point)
1V65_REF: C23.1 C247.1 J26.26 R7.2 R79.1 R125.1 R126.1 R137.1 R145.2 R153.1 R194.1 | length 7342.3
  Layer 1 w12: R7.2@5376.58,3100.66 5376.58,3096.73 5386,3087.31 v1@5386,3069 ; v1(5386.3,3069.04) C23.1@5430.19,3069.04 ; 5389.42,3078.48 5422.77,3078.48 5428.58,3072.66 C23.1@5428.58,3071.04 C23.1@5429.96,3071.04 ; 5425.75,1476.16 5426.46,1476.86 5426.46,1580.87 5473.08,1627.5 5476.83,1627.5 5496,1646.67 v2(5496,1670) ; C23.1@5429.96,3065.73 5433.52,3062.16 5448.71,3062.16 5454.64,3056.23 5493.9,3056.23 v2(5502.27,3064.6) ; v2@5502.27,3064.85 5540.15,3064.85 5601,3004 5694.67,3004 5736.77,3046.1 5736.77,3492.78 5768.5,3524.51 5768.5,3525.39 5794.22,3525.39 J26.26@5797.27,3528.44
  Layer 1 w20: v1(3690.06,3969.54) 3745.51,4024.99 3745.51,4027.78 3760.3,4042.57 4742.24,4042.57 4959.35,3825.46 5095,3689.81 5095,3330.52 v1(5134.79,3290.73) ; v1(5098.27,542.6) 5154.27,542.6 5278.19,666.52 5278.19,1328.59 5425.75,1476.16
  Layer 2 w8: v2(5496,1670) 5612,1786 5612,2436.33 5648,2472.33 5648,2726.3 5654.5,2732.8 5654.5,3005.78 5596.28,3064 v2@5503,3064
  Layer 8 w12: R79.1@5172.26,2922.58 5168.32,2922.58 5150.51,2940.39 5150.51,2984.74 5236.82,3071.04 ; C247.1@5233.27,3447.6 5233.27,3447.37 5225.5,3439.6 5225.27,3439.6 5134.79,3349.12 v1(5134.79,3290.73) 5219.5,3290.73 5232.21,3278.03 5232.21,3144.3 5236.82,3139.69 5236.82,3071.04 ; v1(5386.3,3069.04) 5238.82,3069.04 5236.82,3071.04
  Layer 8 w20: R153.1@3644.98,4004.38 3657.46,4004.38 R153.1@3659.27,4002.57 3663.2,4002.57 3665.02,4000.75 3665.02,3994.58 v1(3690.06,3969.54) 3694.03,3965.57 R145.2@3740.27,3965.57 3744.2,3965.57 3746.02,3963.75 3746.02,3944.16 3768.46,3921.72 3932.41,3921.72 3975.24,3964.55 ; R137.1@3937.07,4004.95 3941.01,4004.95 3953.07,3992.89 3953.07,3986.72 3975.24,3964.55 ; R126.1@4037.57,3964.55 3975.24,3964.55 ; R125.1@5073.27,542.6 v1(5098.27,542.6) ; R194.1@5235.09,3407.6 5235.25,3407.75 C247.1@5235.25,3445.41
3V3_PRI: C22.1 C29.1 C35.2 C36.1 C39.1 C54.1 C61.1 C76.1 C83.1 C98.1 C105.1 C120.1 C129.1 C133.1 C137.1 C139.1 C142.1 C143.1 C144.2 C145.2 C147.1 C162.1 C169.1 C184.1 C198.1 C205.1 C206.1 C208.2 C212.1 C215.2 C239.1 C244.1 C249.1 C251.1 C253.1 J35.2 R13.2 R14.2 R15.2 R20.2 R22.2 R71.2 R138.2 R155.2 R183.2 R203.2 U1.5 U1.14 U4.1 U6.1 U8.10 U8.16 U10.10 U10.16 U12.10 U12.16 U14.10 U14.16 U16.10 U16.16 U18.10 U18.16 U20.10 U20.16 U22.10 U22.16 U24.5 U25.5 U26.5 U29.1 U30.14 U31.14 U32.11 U32.16 U33.11 U33.16 U34.10 U34.16 U36.10 U36.16 U38.10 U38.16 U40.10 U40.16 U42.3 U42.8 U43.5 U44.5 U45.15 U45.16 U46.5 U47.15 U47.16 U48.5 U49.5 U50.5 U51.16 U52.1 | length 7967.4
  Layer 1 w8: v1(4953,2769) 4953.75,2768.25 4998.75,2768.25 U40.10@5001,2766 ; v1(4964,1685) 4964.25,1684.75 5004.75,1684.75 U36.10@5005,1685 ; U40.16@4995.3,2917.5 U40.16@4996.28,2918.48 ; C184.1@5055,2934.68 C184.1@5055,2939 ; v1@5909,288 5909.48,287.52 5946.48,287.52 U14.10@5947,287
  Layer 1 w12: C147.1@5030.57,2069.67 5061.06,2069.67 5063.48,2072.1 v1(5064.57,2072.1) ; v1@5043.27,2612.6 5079.16,2612.6 U31.14@5079.41,2612.35 ; U30.14@5083.27,2382.6 5087.88,2382.6 5088.27,2382.99 v1(5088.27,2397.6) ; v1(5385.01,3403.86) 5386.09,3403.86 5396.8,3393.15 5428,3393.15 C244.1@5430.55,3390.6 ; v1(5948,117) 5948,135.08 U14.16@5949.97,137.05 ; U14.10@5948.27,287.6 5948.82,287.05 U14.10@5949.97,287.05 ; U12.10@5948.27,577.6 5949.82,576.05 U12.10@5949.97,576.05 v1(5989.97,576.05) ; U12.16@5951.72,426.05 v1(5989.97,426.05) ; U24.5@6140.63,3393.86 6139.26,3395.23 6139.26,3454.23 C129.1@6137.89,3455.6 6141.83,3455.6 6156.86,3440.57 R71.2@6204.27,3440.57 ; C239.1@6295,3152 6295.15,3151.85 6320.85,3151.85 v1(6322,3153) ; U8.10@6358.98,3559.74 6361.05,3561.81 6361.05,3591.51 6372.28,3602.74 6495.68,3602.74 6506.91,3591.51 6506.91,3561.81 U8.16@6508.98,3559.74 6508.98,3536.32 6523.56,3521.73 C39.1@6523.56,3479.75 ; U10.16@7081.69,4310.9 7083.76,4308.83 7083.76,4274.93 7090.79,4267.9 7218.39,4267.9 7229.62,4279.13 7229.62,4308.83 U10.10@7231.69,4310.9 ; C83.1@8099,3740.38 8099,3744.32 8116.54,3761.85 8124.15,3761.85 v1@8125,3761 ; C98.1@8106,4159.38 8106,4163.32 8111.81,4169.13 8124.5,4169.13 8126.38,4171 v1@8127,4171 ; C105.1@8110,40 8115.85,34.15 8142.85,34.15 v1(8144,33) 8144.25,33.25 8185.45,33.25 U20.16@8185.7,33.5 ; C120.1@8118,458.38 8143.2,458.38 8150.58,451 v1@8153,451 ; v1(8126,3763) 8127.62,3763 8129.05,3764.43 8167.43,3764.43 U16.16@8168,3765 ; v1@8128,3916 8128.25,3916.25 8169.45,3916.25 U16.10@8169.7,3916.5 ; v1(8129,4172) 8129,4173.22 8146.78,4191 U18.16@8167,4191 ; v1@8130,4340 8131.25,4341.25 8168.95,4341.25 U18.10@8169.7,4340.5 ; v1@8144,184 8144.75,183.25 8185.45,183.25 U20.10@8185.7,183.5 ; v1@8147,618 8147,618.48 8147.77,619.25 8187.45,619.25 U22.10@8187.7,619.5 ; v1(8153,450) 8154.15,451.15 8154.15,459.37 8162.78,468 U22.16@8185,468
  Layer 1 w20: v1@5051.57,3081.1 5057.94,3074.72 5091.46,3074.72 5093.27,3072.91 C169.1@5093.27,3068.98 C169.1@5093.27,3067.6 ; v1(5428.27,3557.6) 5431.74,3554.12 5466.74,3554.12 C249.1@5468.27,3552.6 ; C54.1@7053.65,4378.6 7053.65,4342.22 v1@7057.27,4338.6 ; v1(7057.27,4333.6) U10.16@7082.27,4333.6
  Layer 7 w50: v1@2205,2445 2205,2972.76 2298,3065.76 2298,3800.33 2761.67,4264 3071,4264 ; 3071,4289 3076,4289 3086,4279 ; 3101,4264 3185.5,4179.5 3585.5,4179.5 3687,4281 3831.87,4281 v1(3856.27,4256.6) v1(3878.77,4256.6) v1(3901.27,4256.6)
  Layer 8 w8: v1@5048,3231 5048.1,3231.1 U38.10@5091.57,3231.1 ; v1@5053.27,3077.6 5053.27,3079.1 5055.26,3081.1 U38.16@5091.57,3081.1 ; U43.5@5074.02,714.73 5103.04,714.73 v1(5116.18,701.6) 5136.62,681.16 C205.1@5136.62,677.22 ; U32.16@5179.98,1500.16 5180.04,1500.1 U32.16@5187.79,1500.1 5187.79,1522.12 ; U33.16@5184.93,1677.82 5185,1677.88 5185,1694.31 5180.31,1699 5148,1699 5135.5,1686.5 5135.5,1569.2 5170.6,1534.1 5183.1,1534.1 5187.79,1529.41 5187.79,1522.12 ; v1@5218.27,1377.6 5221.89,1381.22 5221.89,1398.6 5227.16,1403.87 U32.11@5227.16,1444.98 ; v1(5218.27,1552.6) 5187.79,1522.12
  Layer 8 w10: v1@5218.27,1554 5218.27,1562.65 5211.93,1568.98 C145.2@5219.03,1576.09 5224.3,1581.35 U33.11@5224.3,1622.7
  Layer 8 w12: U46.5@3695.04,4134.97 3696.66,4136.58 C212.1@3696.66,4195.95 ; U44.5@3978.35,4136.43 3986.22,4136.43 3992.03,4142.24 3992.03,4150.11 3999.52,4157.6 C206.1@3999.52,4199.95 3999.52,4253.1 3996.02,4256.6 ; C142.1@4963.62,2554.2 4964.45,2553.36 4982.5,2553.36 v1(4983.27,2552.6) ; C143.1@4971.92,2333.72 4971.92,2337.66 C143.1@4977.73,2343.47 ; C143.1@4973.27,2332.6 4977.5,2336.83 4992.5,2336.83 v1(4993.27,2337.6) ; U34.16@5018.27,1922.6 5018.77,1922.1 U34.16@5019.57,1922.1 v1(5064.57,1922.1) ; U34.10@5018.27,2072.6 5018.77,2072.1 U34.10@5019.57,2072.1 v1(5064.57,2072.1) ; v1(5172.27,4256.6) v1@5173.35,4256.6 ; U49.5@5368.51,3428 5376.39,3428 5382.2,3422.19 5382.2,3406.67 v1(5385.01,3403.86) ; 5414.65,4029.58 5420.03,4034.97 U1.5@5420.03,4118 ; U50.5@5426.02,3589.71 U50.5@5433.9,3589.71 ; C61.1@5918.27,413.33 5918.27,417.27 5924.08,423.08 5945.92,423.08 5948.89,426.05 5949.82,426.05 ; C76.1@5921.89,121.51 5925.25,118.15 5946.38,118.15 v1@5948,119.77 ; 5948.27,427.6 5949.82,426.05 ; v1(5989.97,426.05) 5949.82,426.05 ; R183.2@6188,3067 6187.81,3067.19 6187.81,3087.23 v1(6188.25,3087.67) ; v1(6322,3153) 6323.62,3153 6333.07,3162.45 6350.45,3162.45 U48.5@6355,3167
  Layer 8 w20: C139.1@2753.27,4693.98 2753.27,4690.04 2797.9,4645.41 2830.46,4645.41 U29.1@2833.27,4642.6 ; C198.1@3090.27,4304.6 v1(3090.27,4337.6) v1@3090.27,4339.6 ; C212.1@3696.66,4195.95 3696.66,4256.6 ; v1(5428.27,3557.6) U50.5@5428.27,3587.6
  Layer 8 w50: U45.15@2126.26,2453.6 2126.26,2487.87 ; 3696.66,4256.6 v1(3856.27,4256.6) ; v1@3862.55,4256.6 v1(3878.77,4256.6) v1(3901.27,4256.6) 3996.02,4256.6 v1(5127.27,4256.6)
  other v1: 8144,183 5906,288 8145,619 5222,1376 2206.27,2442.6 2206.27,2462.6 5039.41,2612.35 5169.26,2849.6 5032,2935.1 5047,3081.1 5047,3231.1 5303.27,3852.6 8130,3917 3157,4151 3137,4151.6 5127.27,4233.42 5149.77,4233.42 5172.27,4233.42 5149.77,4256.6 6167.78,4262.55 6190.28,4262.55 6212.78,4262.55 6167.78,4285.73 6190.28,4285.73 6212.78,4285.73 8129,4342 7935.02,4350.07 7935.02,4372.6 3153,4402 3153,4422 2829.74,4615.16 2854.74,4615.16 2593.27,4792.6 2618.27,4792.6 2718.27,4932.6 2718.27,4957.6
3V3_REF: C24.2 R8.2 U3.5 | length 1748.5
  Layer 1 w12: R8.2@5519.58,3200.91 5519.99,3201.32 5519.99,3259.86 v1(5520.4,3260.27) ; v1(5611.27,4320.47) 5611.27,4380.6 5653.67,4423 5797.26,4423 5832.66,4387.6 v1(5853.27,4387.6) 5853.65,4387.98 U3.5@5886.09,4387.98 ; U3.5@5885.7,4388.37 U3.5@5886.09,4387.98 ; C24.2@5923.27,4382.6 5920.41,4385.46 5888.61,4385.46 U3.5@5886.09,4387.98
  Layer 2 w12: v1(5611.27,4320.47) 5611.27,4216.74 5701.51,4126.5 5749.96,4126.5 v1(5798.72,4077.74)
  Layer 7 w12: v1(5520.4,3260.27) 5638,3377.87 5638,3528.99 5798.72,3689.71 v1(5798.72,4077.74)
5V_CAN: C140.1 U28.1 U29.8 | length 709.4
  Layer 7 w20: v1(3338.27,4702.6) 3483.27,4702.6 U28.1@3808.27,5027.6
  Layer 8 w20: U29.8@3263.27,4637.6 3275.83,4637.6 3338.27,4700.04 v1(3338.27,4702.6) C140.1@3338.27,4703.98
5V_H_A: C55.1 C58.1 R32.2 U10.1 U10.7 U11.51 | length 305.7
  Layer 1 w20: U10.1@7079.76,4113.24 7081.69,4111.31 U10.1@7081.69,4098.3 ; U10.1@7082.79,4097.2 U10.1@7081.69,4098.3 ; U10.7@7231.69,4098.3 7230.26,4099.73 7230.26,4135.08 7220.05,4145.3 7093.34,4145.3 7083.12,4135.08 7083.12,4099.73 U10.1@7081.69,4098.3
  Layer 8 w12: U11.51@7051,3994 7049.36,3995.64 7049.36,4027.64 v1(7049,4028) 7050.15,4029.15 7050.15,4048.15 v1@7052,4050
  other v1: 7049,4050
5V_H_B: C77.1 C80.1 R42.2 U14.1 U14.7 U15.51 | length 668.9
  Layer 1 w12: U14.7@6161.57,286.05 U14.7@6162.57,287.05 ; U14.1@6162.88,139.12 U14.1@6165,137 ; R42.2@6693,232.38 6696.85,228.53 6696.85,202.15 v1(6698,201) 6697.81,200.81 6697.81,167.19 C80.1@6697.62,167
  Layer 1 w25: U14.1@6181.56,132.62 6195.14,119.04 6210.56,103.62 6219.69,103.62 6220.38,102.93 C77.1@6220.38,100.37 6220.38,100.14 6221.07,99.46 6635.85,99.46 6684.13,147.73 6684.13,148.13 C80.1@6700,164
  Layer 8 w10: U15.51@6697,234 6698.04,232.96 v1(6698,201) v1(6698,201)
  Layer 8 w12: U15.51@6696.21,235.17 6697.52,233.85 U15.51@6698.08,233.3
  other v2: 6172,99 6185,99 6172,112 6185,112 6112,280 6125,280 6112,293 6125,293
5V_H_C: C99.1 C102.1 R52.2 U18.1 U18.7 U19.51 | length 2894.3
  Layer 1 w12: U18.7@8382,4340 8384.57,4342.57 8427.95,4342.57 8429.38,4344 v1(8431,4344) ; U18.1@8384,4190 8406.22,4190 8407.8,4188.43 8407.8,4169.83 v1@8409,4168.62 ; v1(8409,4167) v1@8409,4168.62 ; C99.1@8434.19,4164.13 8413.5,4164.13 v1@8409,4168.62 ; v1@10459,3245 10459,3245.62 10465.5,3252.12 10465.5,3254.49 10468.87,3257.86 10468.87,3262.43 10481.44,3275 C102.1@10485.38,3275 10487,3276.62 10487,3313 R52.2@10488,3314
  Layer 1 w20: C99.1@8440,4154.38 8440,4150.44 C99.1@8441.81,4148.63
  Layer 2 w20: v1@8433,4342 8529.41,4342 8583,4288.41 8583,4086.81 8594.72,4075.1 8668.75,4075.1 8692.85,4051 9528,4051 9761.03,3817.97 ccw(c9844.57,3838.57) 9823.97,3755.03 10180,3399 10381,3399 10459.5,3320.5 10459.5,3248.5 v1@10461.51,3246.49
  Layer 8 w12: U19.51@10459.86,3278.02 10460.43,3277.45 v1@10460.43,3246.43 ; U19.51@10459.93,3279.07 U19.51@10461,3278
  other v1: 10461,3246
5V_H_D: C121.1 C124.1 R62.2 U22.1 U22.7 U23.51 | length 257.9
  Layer 1 w12: U22.7@8400.3,619.5 8402.37,617.43 8455.57,617.43 C121.1@8459,614 ; U22.1@8402,469 8402.75,469.75 8447.75,469.75 v1(8448,470) ; C121.1@8458,617 C121.1@8459.81,615.19
  Layer 1 w20: C124.1@9797.27,1252.84 9797.27,1248.91 9799.08,1247.09 9828.77,1247.09 9818.15,1257.72 9818.15,1285.79 9816.34,1287.6 R62.2@9812.4,1287.6
  Layer 1 w25: 9828.77,1247.09 v3(9842.27,1233.6)
  Layer 8 w10: v3(9842.27,1233.6) 9842.27,1230.89 9852.38,1220.78 9852.38,1198.73 U23.51@9855.25,1195.86
  other v2: 8471,608 8470.58,621.39
5V_H_PFC_1: C163.1 C166.1 R103.2 U36.1 U36.7 U37.51 | length 522.7
  Layer 1 w12: R103.2@4404,1641 R103.2@4404,1640.38 4404,1636.44 4479.43,1561.01 4491.97,1561.01 v1(4493.12,1559.87) ; C163.1@4742,1684 4742.25,1684.25 4792.45,1684.25 U36.7@4792.7,1684.5 4793.45,1685.25 v1@4834.75,1685.25 ; U36.1@4786,1835 4788.57,1832.43 4827.97,1832.43 4835.7,1824.7 4835.7,1689.32 4834,1687.62 v1(4834,1686)
  Layer 8 w12: U37.51@4459,1560 4459.43,1559.57 4492.82,1559.57 v1(4493.12,1559.87) 4523.9,1559.87 4532.03,1568 C166.1@4566,1568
